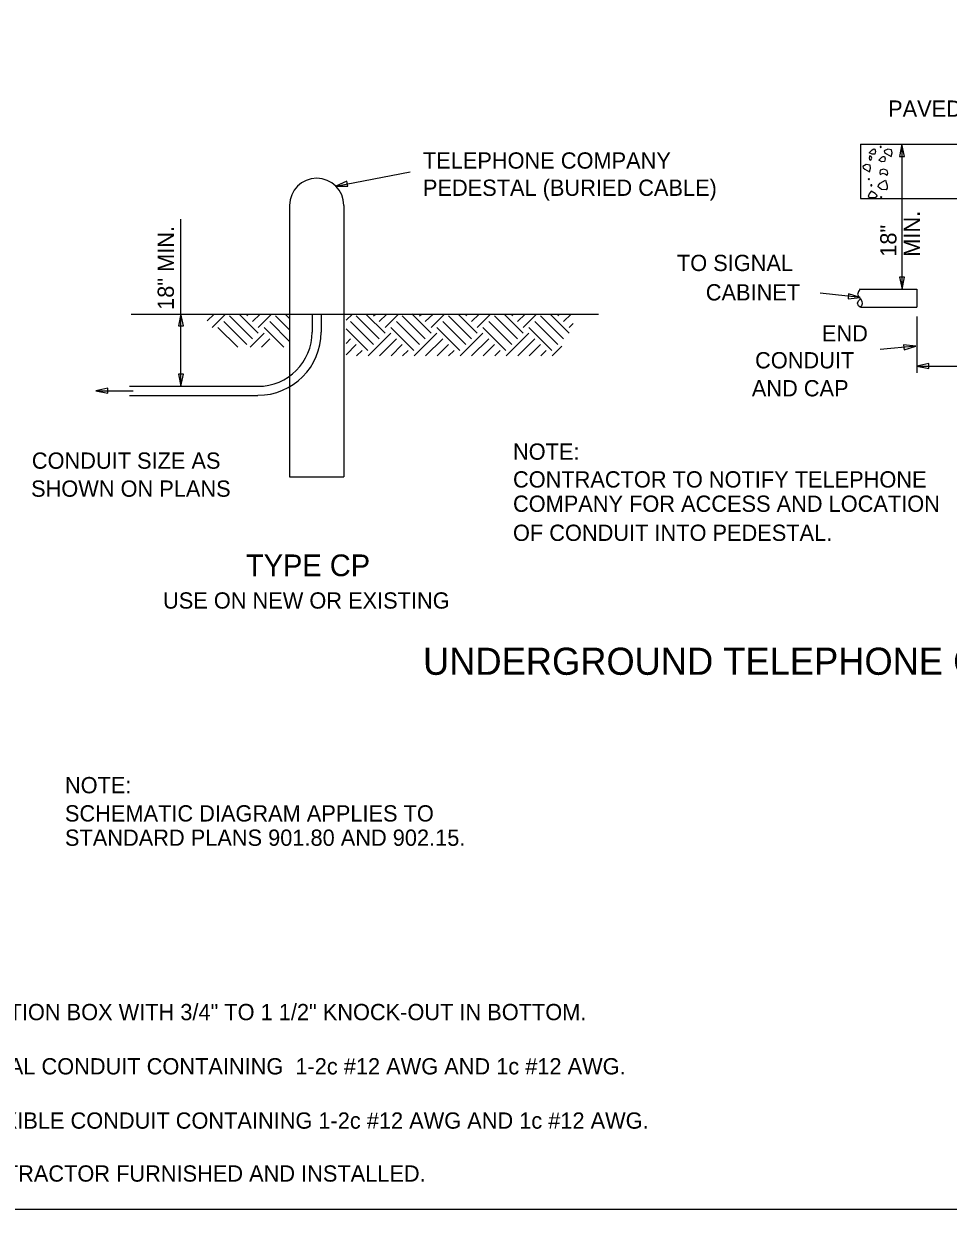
# Model space of a CAD drawing. Extents: x -439.1 to -407.9, y -458.1 to -436.2.
# Drawn here: x -424.94 to -416.41, y -458.05 to -447.12 of the extents above; entities that cross this region are included whole.
import ezdxf

# ---------------------------------------------------------------- set-up
doc = ezdxf.new("R2010")
doc.units = 0
doc.layers.add('Draft_Named_Boundary', color=7, linetype='Continuous')
doc.layers.add('Level 4', color=7, linetype='Continuous')

msp = doc.modelspace()

# ---------------------------------------------------------------- linework, layer by layer
at = {"layer": 'Draft_Named_Boundary'}
msp.add_lwpolyline([(-439.109, -458.051), (-407.859, -458.051), (-407.859, -437.676), (-439.109, -437.676)], close=True, dxfattribs=at)
at = {"layer": 'Level 4'}
for p, q in [((-417.224, -448.236), (-412.328, -448.236)), ((-417.224, -448.236), (-417.224, -448.736)), ((-416.842, -448.236), (-416.842, -449.57)), ((-422.06, -448.621), (-421.374, -448.49)), ((-417.224, -448.736), (-415.703, -448.736)), ((-422.485, -448.8), (-422.485, -449.8)), ((-421.985, -448.8), (-421.985, -449.8)), ((-423.487, -450.466), (-423.487, -448.925)), ((-417.226, -449.649), (-417.595, -449.609)), ((-417.224, -449.57), (-416.703, -449.57)), ((-416.703, -449.57), (-416.703, -449.736)), ((-423.945, -449.8), (-419.638, -449.8)), ((-423.245, -449.864), (-423.181, -449.8)), ((-423.198, -449.923), (-423.074, -449.8)), ((-422.826, -450.029), (-423.039, -449.817)), ((-422.773, -449.976), (-422.95, -449.8)), ((-422.879, -449.817), (-422.862, -449.8)), ((-422.826, -449.87), (-422.756, -449.8)), ((-422.773, -449.923), (-422.65, -449.8)), ((-422.485, -449.946), (-422.614, -449.817)), ((-422.485, -449.84), (-422.525, -449.8)), ((-422.485, -449.8), (-422.485, -451.3)), ((-422.277, -449.8), (-422.277, -449.966)), ((-422.193, -449.8), (-422.193, -449.966)), ((-421.985, -449.8), (-421.985, -451.3)), ((-421.964, -449.858), (-421.906, -449.8)), ((-421.658, -450.029), (-421.87, -449.817)), ((-421.605, -449.976), (-421.781, -449.8)), ((-421.711, -449.817), (-421.694, -449.8)), ((-421.658, -449.87), (-421.588, -449.8)), ((-421.605, -449.923), (-421.482, -449.8)), ((-421.234, -450.029), (-421.446, -449.817)), ((-421.18, -449.976), (-421.357, -449.799)), ((-421.287, -449.817), (-421.269, -449.8)), ((-421.234, -449.87), (-421.163, -449.8)), ((-421.18, -449.923), (-421.057, -449.8)), ((-420.809, -450.029), (-421.021, -449.817)), ((-420.756, -449.976), (-420.932, -449.8)), ((-420.862, -449.817), (-420.845, -449.8)), ((-420.809, -449.87), (-420.739, -449.8)), ((-420.756, -449.923), (-420.633, -449.8)), ((-420.385, -450.029), (-420.597, -449.817)), ((-420.332, -449.976), (-420.508, -449.8)), ((-420.438, -449.817), (-420.421, -449.8)), ((-420.385, -449.87), (-420.315, -449.8)), ((-420.332, -449.923), (-420.209, -449.8)), ((-419.961, -450.029), (-420.173, -449.817)), ((-419.908, -449.976), (-420.084, -449.8)), ((-420.014, -449.817), (-419.997, -449.8)), ((-419.961, -449.87), (-419.891, -449.8)), ((-417.224, -449.736), (-416.703, -449.736)), ((-416.704, -449.824), (-416.704, -450.342)), ((-422.963, -450.105), (-423.145, -449.923)), ((-422.879, -450.082), (-423.092, -449.87)), ((-422.539, -450.105), (-422.72, -449.923)), ((-422.485, -450.052), (-422.667, -449.87)), ((-421.764, -450.135), (-421.964, -449.935)), ((-421.711, -450.082), (-421.923, -449.87)), ((-421.34, -450.135), (-421.552, -449.923)), ((-421.287, -450.082), (-421.499, -449.87)), ((-420.915, -450.135), (-421.127, -449.923)), ((-420.862, -450.082), (-421.074, -449.87)), ((-420.491, -450.135), (-420.703, -449.923)), ((-420.438, -450.082), (-420.65, -449.87)), ((-420.067, -450.135), (-420.279, -449.923)), ((-420.014, -450.082), (-420.226, -449.87)), ((-419.908, -449.923), (-419.872, -449.887)), ((-422.849, -450.105), (-422.72, -449.976)), ((-422.743, -450.105), (-422.667, -450.029)), ((-421.964, -450.071), (-421.923, -450.029)), ((-421.761, -450.186), (-421.552, -449.976)), ((-421.655, -450.186), (-421.499, -450.029)), ((-421.337, -450.186), (-421.127, -449.976)), ((-421.231, -450.186), (-421.074, -450.029)), ((-420.913, -450.186), (-420.703, -449.976)), ((-420.807, -450.186), (-420.65, -450.029)), ((-420.488, -450.186), (-420.279, -449.976)), ((-420.382, -450.186), (-420.226, -450.029)), ((-421.964, -450.177), (-421.87, -450.082)), ((-421.867, -450.186), (-421.817, -450.135)), ((-421.549, -450.186), (-421.446, -450.082)), ((-421.443, -450.186), (-421.393, -450.135)), ((-421.125, -450.186), (-421.021, -450.082)), ((-421.019, -450.186), (-420.968, -450.135)), ((-420.701, -450.186), (-420.597, -450.082)), ((-420.594, -450.186), (-420.544, -450.135)), ((-420.276, -450.186), (-420.173, -450.082)), ((-420.17, -450.186), (-420.12, -450.135)), ((-420.064, -450.186), (-419.975, -450.096)), ((-416.713, -450.095), (-417.043, -450.128)), ((-416.704, -450.279), (-415.703, -450.279)), ((-423.961, -450.466), (-422.777, -450.466)), ((-424.27, -450.507), (-423.925, -450.507)), ((-423.961, -450.55), (-422.777, -450.55)), ((-422.485, -451.3), (-421.985, -451.3))]:
    msp.add_line(p, q, dxfattribs=at)
for points in [[(-417.143, -448.313), (-417.115, -448.287), (-417.101, -448.279), (-417.09, -448.28), (-417.084, -448.302), (-417.091, -448.326), (-417.115, -448.327), (-417.143, -448.313)], [(-416.942, -448.348), (-416.931, -448.314), (-416.937, -448.286), (-416.973, -448.282), (-417.004, -448.297), (-417.001, -448.31), (-416.985, -448.324), (-416.942, -448.348)], [(-416.819, -448.347), (-416.842, -448.236), (-416.865, -448.347)], [(-417.119, -448.362), (-417.126, -448.349), (-417.136, -448.343), (-417.142, -448.349), (-417.145, -448.36), (-417.142, -448.375), (-417.134, -448.382), (-417.125, -448.375), (-417.119, -448.362)], [(-417.055, -448.381), (-417.027, -448.355), (-417.013, -448.347), (-417.002, -448.349), (-416.995, -448.371), (-417.003, -448.394), (-417.027, -448.396), (-417.055, -448.381)], [(-417.141, -448.489), (-417.13, -448.456), (-417.135, -448.428), (-417.172, -448.423), (-417.203, -448.439), (-417.2, -448.452), (-417.184, -448.466), (-417.141, -448.489)], [(-417.043, -448.474), (-417.046, -448.499), (-417.041, -448.514), (-417.029, -448.509), (-417.013, -448.502), (-416.992, -448.511), (-416.977, -448.519), (-416.972, -448.502), (-416.979, -448.477), (-417.008, -448.465), (-417.043, -448.474)], [(-421.956, -448.577), (-422.06, -448.621), (-421.947, -448.623)], [(-416.994, -448.567), (-416.979, -448.617), (-416.978, -448.64), (-416.987, -448.655), (-417.029, -448.653), (-417.062, -448.628), (-417.059, -448.611), (-417.041, -448.594), (-416.994, -448.567)], [(-417.124, -448.667), (-417.145, -448.692), (-417.152, -448.716), (-417.136, -448.725), (-417.111, -448.727), (-417.086, -448.723), (-417.071, -448.714), (-417.074, -448.703), (-417.088, -448.69), (-417.124, -448.667)], [(-416.863, -449.459), (-416.84, -449.57), (-416.817, -449.459)], [(-417.338, -449.66), (-417.226, -449.649), (-417.333, -449.614)], [(-423.464, -449.91), (-423.487, -449.799), (-423.51, -449.91)], [(-416.821, -450.129), (-416.713, -450.095), (-416.826, -450.084)], [(-416.593, -450.256), (-416.704, -450.279), (-416.593, -450.302)], [(-423.51, -450.355), (-423.487, -450.466), (-423.464, -450.355)], [(-424.16, -450.482), (-424.27, -450.507), (-424.159, -450.528)]]:
    msp.add_lwpolyline(points, close=True, dxfattribs=at)
msp.add_lwpolyline([(-417.225, -449.569), (-417.243, -449.593), (-417.25, -449.619), (-417.239, -449.641), (-417.222, -449.661), (-417.211, -449.682), (-417.209, -449.707), (-417.215, -449.725), (-417.225, -449.736), (-417.241, -449.725), (-417.251, -449.701), (-417.242, -449.678), (-417.222, -449.661)], dxfattribs=at)
for centre, radius, start, end in [((-417.037, -448.26), 0.00521, 0, 180), ((-417.037, -448.26), 0.00521, 180, 0), ((-422.235, -448.799), 0.25, 0, 180), ((-417.147, -448.557), 0.00521, 0, 180), ((-417.147, -448.557), 0.00521, 180, 0), ((-417.123, -448.614), 0.00521, 0, 180), ((-417.123, -448.614), 0.00521, 180, 0), ((-417.033, -448.723), 0.00521, 0, 180), ((-417.033, -448.723), 0.00521, 180, 0), ((-422.777, -449.966), 0.5, 270, 0), ((-422.777, -449.966), 0.583, 270, 360)]:
    msp.add_arc(centre, radius, start, end, dxfattribs=at)

# ---------------------------------------------------------------- texts
for s, height, p in [('PAVED AREA', 0.15, (-416.969, -447.982)), ('TELEPHONE COMPANY', 0.15, (-421.256, -448.46)), ('PEDESTAL (BURIED CABLE)', 0.15, (-421.256, -448.711)), ('TO SIGNAL', 0.15, (-418.915, -449.404)), ('CABINET', 0.15, (-418.649, -449.675)), ('END', 0.15, (-417.579, -450.053)), ('CONDUIT', 0.15, (-418.195, -450.301)), ('AND CAP', 0.15, (-418.225, -450.559)), ('NOTE:', 0.15, (-420.426, -451.143)), ('CONDUIT SIZE AS', 0.15, (-424.86, -451.226)), ('CONTRACTOR TO NOTIFY TELEPHONE', 0.15, (-420.426, -451.399)), ('SHOWN ON PLANS', 0.15, (-424.867, -451.484)), ('COMPANY FOR ACCESS AND LOCATION', 0.15, (-420.426, -451.623)), ('OF CONDUIT INTO PEDESTAL.', 0.15, (-420.426, -451.891)), ('TYPE CP', 0.2, (-422.887, -452.216)), ('USE ON NEW OR EXISTING', 0.15, (-423.651, -452.515)), ('UNDERGROUND TELEPHONE CONNECTION', 0.25, (-421.255, -453.125)), ('NOTE:', 0.15, (-424.555, -454.217)), ('SCHEMATIC DIAGRAM APPLIES TO', 0.15, (-424.555, -454.477)), ('STANDARD PLANS 901.80 AND 902.15.', 0.15, (-424.555, -454.701)), ('1 12" x 12" x 6" JUNCTION BOX WITH 3/4" TO 1 1/2" KNOCK-OUT IN BOTTOM.', 0.15, (-427.027, -456.308)), ('2 3/4" MINIMUM METAL CONDUIT CONTAINING  1-2c #12 AWG AND 1c #12 AWG.', 0.15, (-427.027, -456.808)), ('3 3/4" MINIMUM FLEXIBLE CONDUIT CONTAINING 1-2c #12 AWG AND 1c #12 AWG.', 0.15, (-427.027, -457.308)), ('ALL ITEMS CONTRACTOR FURNISHED AND INSTALLED.', 0.15, (-426.636, -457.796))]:
    msp.add_text(s, height=height, dxfattribs=at).set_placement(p)
for s, p in [('MIN.', (-416.675, -449.272)), ('18" MIN.', (-423.551, -449.762)), ('18" ', (-416.892, -449.272))]:
    msp.add_text(s, height=0.15, rotation=90, dxfattribs=at).set_placement(p)

doc.saveas('drawing.dxf')
